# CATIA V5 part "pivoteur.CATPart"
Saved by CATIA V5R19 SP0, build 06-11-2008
Part number: Pivoteur
Bounding box of the stored display mesh (mm): x -307.5 to 9, y -50 to 50, z -130 to 128
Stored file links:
  E:\IAO_2010\iao\IAO_MMS_Groupe2\IAO_MMS_Groupe2\svallart\Assemblage\pivoteur.CATPart
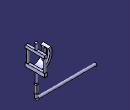
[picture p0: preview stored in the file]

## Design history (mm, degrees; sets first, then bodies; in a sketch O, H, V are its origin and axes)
Body1 (main body)
  Sketch1 on xy-plane, origin (0, 0, 0), H (1, 0, 0), V (0, 1, 0)
    circle A1 centre (0, 0) radius 6.5
    radius A1 = 6.5
  Pad1: profile Sketch1, direction (0, 0, -1), length 50
  Plane1: type Offset, RefPlane end face of Pad1, Offset 5, reversed
  Sketch2 on yz-plane, origin (0, 0, 0), H (0, 1, 0), V (0, 0, 1)
    line L1 (0, 258.7847) -> (0, -808.3505)
    point P1 (0, 258.7847)
    coincidence: P1 V
    vertical: L1 V
  Sketch3 on Plane1, origin (0, 0, -55), H (1, 0, 0), V (0, 1, 0)
    circle A1 centre (0, 0) radius 9
    radius A1 = 9
  Loft1: solid, Sections (edge [end face of Pad1 | face of Pad1 from Sketch1.A1]; Sketch3), Spine Sketch2
  Pad2: profile face of Loft1, direction along face of Loft1, length 40
  Sketch4 on yz-plane, origin (0, 0, 0), H (0, 1, 0), V (0, 0, 1)
    line L1 (9.361, 0) -> (50, 0)
    line L2 (50, 0) -> (50, 18)
    line L3 (50, 18) -> (-50, 18)
    line L4 (-50, 18) -> (-50, 0)
    point P5 (-50, 0)
    line L5 (-50, 0) -> (-9.361, 0)
    line L6 (-9.361, 0) -> (-9.361, 0)
    line L7 (-9.361, 0) -> (9.361, 0)
    line L8 (9.361, 0) -> (9.361, 0)
    reference projected line E1 (-6.5, 0) -> (6.5, 0) from edge [face of Pad1 from Sketch1.A1 | start face of Pad1]
    length L2 = 18
    distance L2 L4 = 100
    distance L1 L7 = 0
    horizontal: L1 H, L3 H, L5 H, L7 H
    vertical: L2 V, L4 V, L6 V, L8 V
    coincidence: P5 L1, L7 E1
    symmetry: L4 L2 V, L6 L8 V
  Pad3: profile Sketch4, direction (1, 0, 0), length 6.5, mirrored extent
  Sketch5 on zx-plane, origin (0, 0, 0), H (-1, 0, 0), V (0, 0, 1)
    arc A1 centre (0, 65.0757) radius 50 from (6.5, 15.5) to (43.4251, 89.86) ccw
    point P1 (0, 65.0757)
    point P2 (6.5, 15.5)
    line L1 (6.5, 15.5) -> (6.5, 2.4119)
    arc A2 centre (0, 65.0757) radius 63 from (6.5, 2.4119) to (54.7156, 96.3039) ccw
    line L2 (43.4251, 89.86) -> (54.7156, 96.3039)
    distance L1 V = 6.5
    distance H P2 = 15.5
    distance A2 A1 = 13
    radius A1 = 50
    vertical: L1 V
    concentricity: A2 A1
    coincidence: L2 P1, P1 V
  Pad4: profile Sketch5, direction (0, 1, 0), length 20, mirrored extent
  Sketch6 on end face of Pad3, origin (6.5, 0, 0), H (0, 1, 0), V (0, 0, 1)
  Sketch7 on end face of Pad2, origin (0, 0, -95), H (1, 0, 0), V (0, -1, 0)
    circle A1 centre (0, 0) radius 7.5
    reference projected circle E1 centre (0.0001, 0) radius 9 from edge [end face of Pad2 | face of Pad2]
    radius A1 = 7.5
    radius E1 = 9 (reference)
  Pad5: profile Sketch7, direction (0, 0, -1), length 20
  Plane2: type Offset, RefPlane yz-plane, Offset -7.5
  Sketch8 on Plane2, origin (-7.5, 0, 0), H (0, 1, 0), V (0, 0, 1)
    point P1 (20.1042, -115)
    point P2 (-20.1655, -115)
    reference projected line E1 (7.5, -115) -> (-7.5, -115) from edge [face of Pad5 from Sketch7.A1 | end face of Pad5]
    reference projected line E2 (7.5, -115) -> (-7.5, -115) from edge [face of Pad5 from Sketch7.A1 | end face of Pad5]
    coincidence: P2 E1, P1 E2
  Line1: type PtPt, FirstPoint Sketch8.P2, SecondPoint Sketch8.P1
  Sketch9 on end face of Pad5, origin (0, 0, -115), H (1, 0, 0), V (0, -1, 0)
    circle A1 centre (0, 0) radius 7.5
    radius A1 = 7.5
  Shaft1: profile Sketch9, axis Line1, angle 90
  Sketch10 on face of Shaft1, origin (-7.5, 0, 0), H (0, -1, 0), V (0, 0, 1)
    circle A1 centre (0, -122.5) radius 7.5
    reference projected circle E1 centre (0, -122.5) radius 7.5 from edge [face of Shaft1 from Sketch9.A1 | face of Shaft1]
    coincidence: A1 E1
  Pad6: profile Sketch10, direction (-1, 0, 0), length 300
  Sketch11 on face of Pad3 from Sketch4.L3, origin (0, 0, 18), H (1, 0, 0), V (0, 1, 0)
    circle A1 centre (0, 43.5) radius 6.5
    point P1 (0, 43.5)
    circle A2 centre (0, -43.5) radius 6.5
    point P2 (0, -43.5)
    reference projected line E1 (6.5, 70.0307) -> (6.5, -70.0307) from edge [face of Pad3 from Sketch4.L3 | end face of Pad3]
    reference projected line E2 (6.5, 70.0307) -> (6.5, -70.0307) from edge [face of Pad3 from Sketch4.L3 | end face of Pad3]
    reference projected line E3 (-6.5, -50) -> (6.5, -50) from edge [face of Pad3 from Sketch4.L4 | face of Pad3 from Sketch4.L3]
    reference projected line E4 (-6.5, 50) -> (6.5, 50) from edge [face of Pad3 from Sketch4.L3 | face of Pad3 from Sketch4.L2]
    coincidence: P1 V, P2 V
    tangency: A1 E1, A2 E2, A2 E3, A1 E4
  Pad7: profile Sketch11, direction (0, 0, 1), length 65
  Sketch12 on face of Pad3 from Sketch4.L4, origin (0, -50, 0), H (1, 0, 0), V (0, 0, 1)
    reference projected line E1 (6.5, 34.6245) -> (6.5, 20.069) from edge [face of Pad3 from Sketch4.L4 | end face of Pad3]
    reference projected line E2 (-6.5, 34.6245) -> (-6.5, 20.069) from edge [start face of Pad3 | face of Pad3 from Sketch4.L4]
    reference projected line E3 (-6.5, 0) -> (6.5, 0) from edge [face of Pad3 from Sketch4.L5 | face of Pad3 from Sketch4.L4]
    reference projected line E4 (-6.5, 18) -> (6.5, 18) from edge [face of Pad3 from Sketch4.L4 | face of Pad3 from Sketch4.L3]
    line L1 (-6.5, 98) -> (6.5, 98)
    line L2 (6.5, 98) -> (6.5, 83)
    line L3 (6.5, 83) -> (-6.5, 83)
    line L4 (-6.5, 83) -> (-6.5, 98)
    reference projected line E5 (-6.5, 83) -> (6.5, 83) from edge [face of Pad7 from Sketch11.A2 | end face of Pad7]
    reference projected line E6 through (0, 0) direction (0, 1) from axis of face of Pad7 from Sketch11.A2
    distance E1 E2 = 13 (reference)
    distance E3 E4 = 18 (reference)
    length L1 = 13
    length L2 = 15
    horizontal: L1 H, L3 H
    vertical: L2 V, L4 V
    coincidence: L3 E5
    symmetry: L4 L2 E6
  Pad8: profile Sketch12, direction (0, 1, 0), length 100
  Sketch13 on face of Pad8 from Sketch12.L1, origin (0, 0, 98), H (1, 0, 0), V (0, 1, 0)
    circle A1 centre (0, 0) radius 6.5
    reference projected line E1 (6.5, -70) -> (6.5, 70) from edge [face of Pad8 from Sketch12.L2 | face of Pad8 from Sketch12.L1]
    distance A1 E1 = 0
  Pad9: profile Sketch13, direction (0, 0, 1), length 30
  Sketch14 on yz-plane, origin (0, 0, 0), H (0, 1, 0), V (0, 0, 1)
    line L1 (-10, 39.1126) -> (-10, 73.4101)
    arc A1 centre (0, 73.4101) radius 10 from (-10, 73.4101) to (10, 73.4101) cw
    line L2 (10, 73.4101) -> (10, 39.1126)
    arc A2 centre (0, 39.1126) radius 10 from (10, 39.1126) to (-10, 39.1126) cw
    distance V L2 = 10
    vertical: L1 V
    tangency: A1 L1, L2 A1, A2 L1, A2 L2
    symmetry: L2 L1 V
  Pocket1: profile Sketch14, direction (-1, 0, 0), through (limit type 3)
  Plane3: type Offset, RefPlane yz-plane, Offset -56.5
  Point1: type OnPlane, Support Plane3, H 0, V 20, Direction (0, 1, 0)
  Point2: type OnPlane, Support Plane3, H 0, V 150, Direction (0, 1, 0)
  Line2: type PtPt, FirstPoint Point1, SecondPoint Point2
